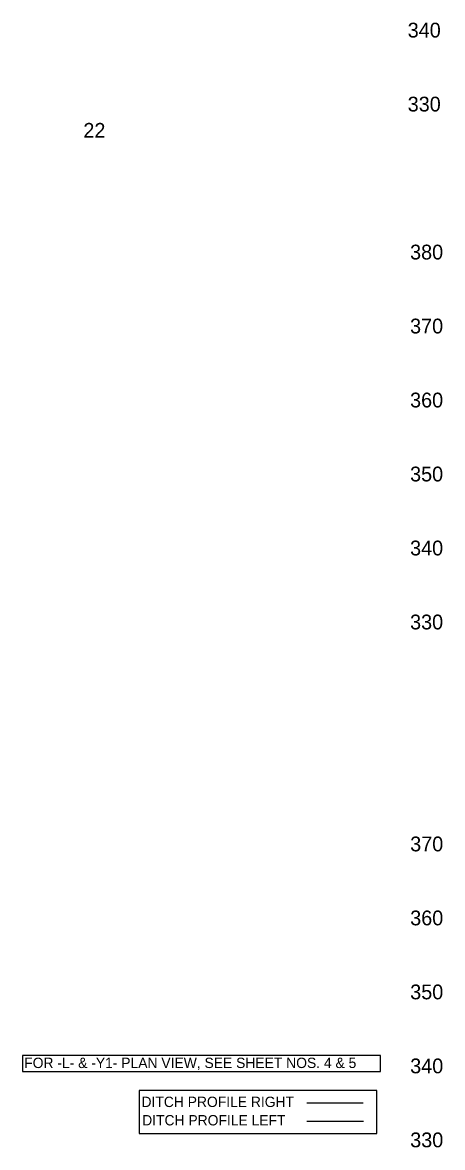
# Model space of a CAD drawing. Extents: x 2095765 to 2097235, y 866038 to 867018.
# Drawn here: x 2096951 to 2097235, y 866038 to 866799 of the extents above; entities that cross this region are included whole.
import ezdxf

# ---------------------------------------------------------------- set-up
doc = ezdxf.new("R2010")
doc.units = 0
for name, color, linetype in [('Exist Vertical Profile Horizontal Axis Label Major', 7, 'Continuous'), ('Exist Vertical Profile Vertical Axis Label', 7, 'Continuous'), ('Prop Grid Mask', 7, 'Continuous'), ('Prop PFL Text', 7, 'Continuous'), ('Prop Vertical Profile Ditch Grade Left', 7, 'Continuous'), ('Prop Vertical Profile Ditch Grade Left Label', 7, 'Continuous'), ('Prop Vertical Profile Ditch Grade Right', 7, 'Continuous'), ('Prop VPI Ditch Grade Right Label', 7, 'Continuous')]:
    doc.layers.add(name, color=color, linetype=linetype)

msp = doc.modelspace()

# ---------------------------------------------------------------- linework, layer by layer
at = {"layer": 'Exist Vertical Profile Vertical Axis Label'}
msp.add_lwpolyline([(2097029.82, 866047.81), (2097190.38, 866047.81), (2097190.38, 866077), (2097029.82, 866077)], close=True, dxfattribs=at)
at = {"layer": 'Prop Grid Mask'}
msp.add_lwpolyline([(2096951.14, 866089.79), (2097192.93, 866089.79), (2097192.93, 866100.67), (2096951.14, 866100.67)], close=True, dxfattribs=at)
at = {"layer": 'Prop Vertical Profile Ditch Grade Left'}
msp.add_line((2097142.99, 866056.26), (2097181.29, 866056.26), dxfattribs=at)
at = {"layer": 'Prop Vertical Profile Ditch Grade Right'}
msp.add_line((2097142.98, 866068.52), (2097181.12, 866068.52), dxfattribs=at)

# ---------------------------------------------------------------- texts
at = {"layer": 'Exist Vertical Profile Horizontal Axis Label Major'}
msp.add_text('22', height=10, dxfattribs=at).set_placement((2096992.22, 866720.82))
at = {"layer": 'Exist Vertical Profile Vertical Axis Label'}
for s, p in [('340', (2097211.18, 866788.57)), ('330', (2097211.18, 866738.57)), ('380', (2097212.8, 866638.57)), ('370', (2097212.8, 866588.57)), ('360', (2097212.8, 866538.57)), ('350', (2097212.8, 866488.57)), ('340', (2097212.8, 866438.57)), ('330', (2097212.8, 866388.57)), ('370', (2097212.88, 866238.57)), ('360', (2097212.88, 866188.57)), ('350', (2097212.88, 866138.57)), ('340', (2097212.88, 866088.57)), ('330', (2097212.88, 866038.57))]:
    msp.add_text(s, height=10, dxfattribs=at).set_placement(p)
at = {"layer": 'Prop PFL Text'}
msp.add_text('FOR -L- & -Y1- PLAN VIEW, SEE SHEET NOS. 4 & 5', height=7, dxfattribs=at).set_placement((2096952.3, 866092.13))
at = {"layer": 'Prop Vertical Profile Ditch Grade Left Label'}
msp.add_text('DITCH PROFILE LEFT', height=7, rotation=360, dxfattribs=at).set_placement((2097031.94, 866053.35))
at = {"layer": 'Prop VPI Ditch Grade Right Label'}
msp.add_text('DITCH PROFILE RIGHT', height=7, rotation=360, dxfattribs=at).set_placement((2097031.47, 866065.78))

doc.saveas('drawing.dxf')
